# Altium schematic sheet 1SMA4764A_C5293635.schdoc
size 127 x 101 mm
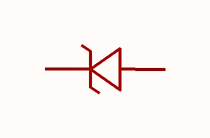
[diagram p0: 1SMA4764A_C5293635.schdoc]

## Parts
D?  1sma4764a_c5293635  [SMAG_L4.3-W2.6-LS5.3-RD]  (value not drawn)

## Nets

Not connected (* = marked no-connect by the designer): D? 1(K) 2(A)

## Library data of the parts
D? = 1sma4764a_c5293635: 二极管配置:1个独立式;稳压值(标称值):100V;稳压值(范围值):-;耗散功率(Pd):1W;; Manufacturer: CJ(江苏长电/长晶); AddInBom: yes; ModelId: 3cd8680d946b497db8ea5837610a9736; ModelTransform: 208.661,102.362,0,0,0,0,0,0,0; Diode Configuration: 1个独立式; Zener Voltage(Nom): 100V; Reverse Leakage Current (Ir): 100nA; Pd - Power Dissipation: 1W; Impedance(Zzt): 350Ω; Impedance(Zzk): 3kΩ; Operating Junction Temperature Range: -55℃~+150℃; Tolerance: ±5%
